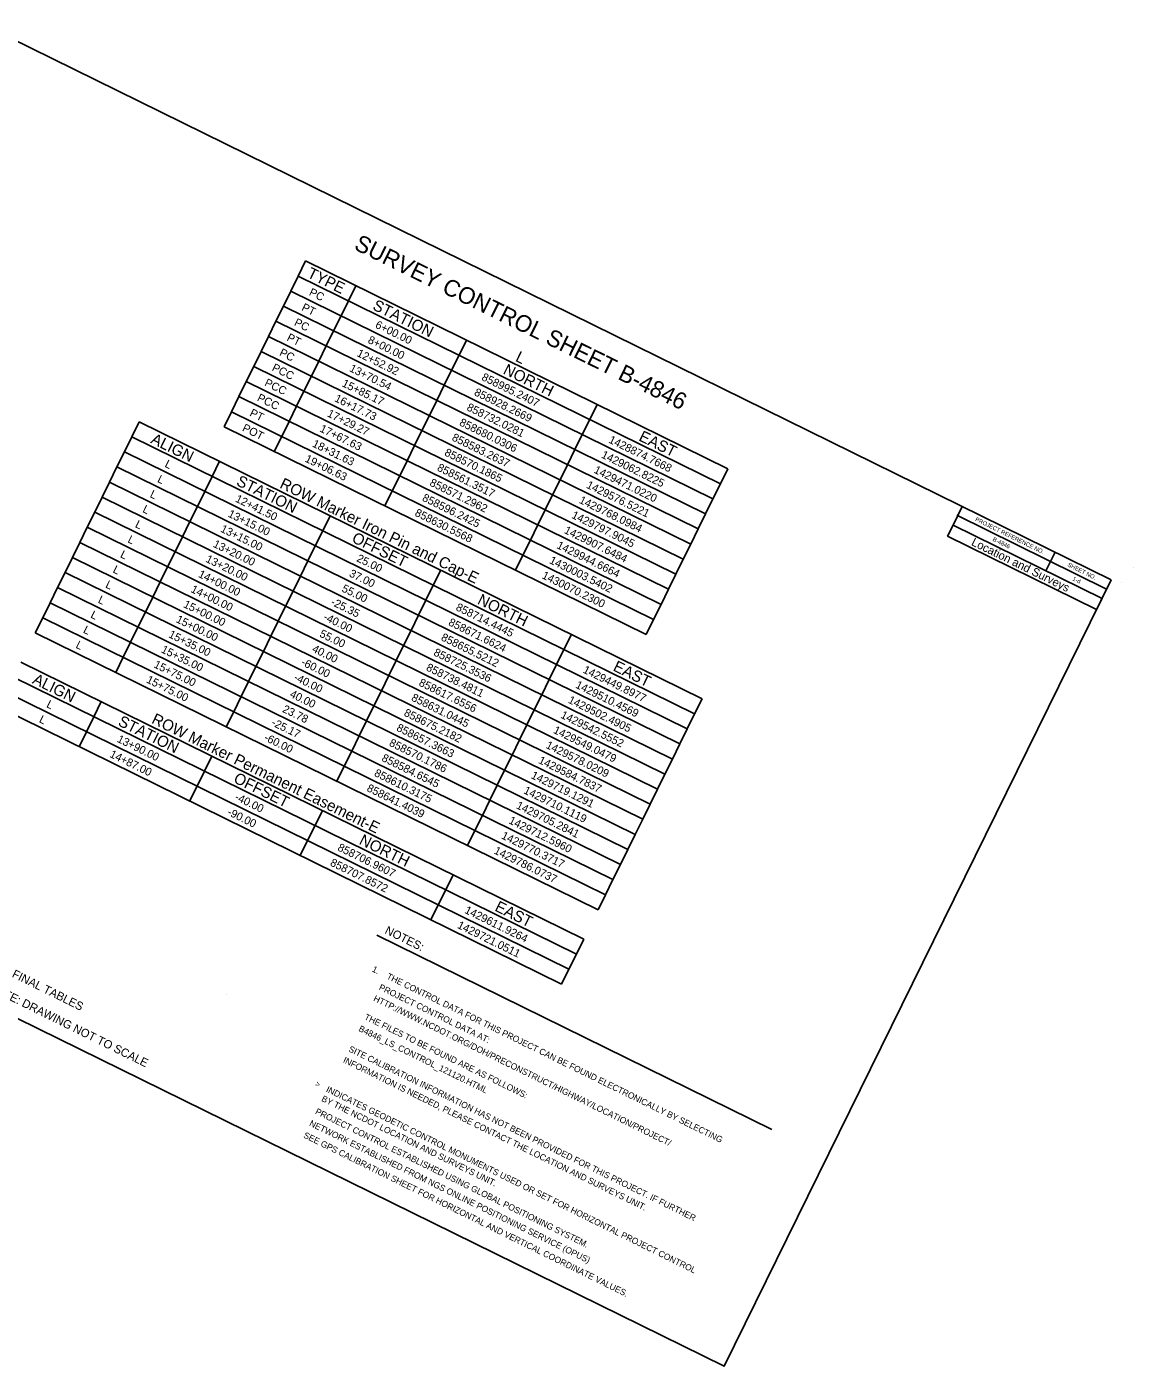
# Model space of a CAD drawing. Extents: x 1428428 to 1430511, y 857911 to 859585.
# Drawn here: x 1429129 to 1430511, y 857911 to 859585 of the extents above; entities that cross this region are included whole.
import ezdxf

# ---------------------------------------------------------------- set-up
doc = ezdxf.new("R2010")
doc.units = 0
for name, color, linetype in [('CTL Sheet Border CELL', 7, 'Continuous'), ('CTL Sheet Notes CELL', 7, 'Continuous'), ('CTL Sheet Table Cell', 7, 'Continuous'), ('CTL Sheet Text', 7, 'Continuous'), ('Sheet Title CELL', 7, 'Continuous')]:
    doc.layers.add(name, color=color, linetype=linetype)

msp = doc.modelspace()

# ---------------------------------------------------------------- linework, layer by layer
at = {"layer": 'CTL Sheet Border CELL'}
for p, q in [((1430297.8, 858985.3), (1430286.3, 858961.8)), ((1430291, 858974.1), (1430478.3, 858881.9)), ((1430413.8, 858928.2), (1430402.3, 858904.8)), ((1430511.5, 858909.2), (1430511.5, 858909.2)), ((1430496.9, 858890.3), (1430496.9, 858890.3)), ((1430496.9, 858890.3), (1430496.9, 858890.3))]:
    msp.add_line(p, q, dxfattribs=at)
for points in [[(1430484, 858893.6), (1429079.6, 859584.7), (1428595.9, 858601.6), (1430000.3, 857910.6)], [(1430286.3, 858961.8), (1430472.5, 858870.2), (1430465.7, 858856.4), (1430279.5, 858948.1)]]:
    msp.add_lwpolyline(points, close=True, dxfattribs=at)
at = {"layer": 'CTL Sheet Notes CELL'}
msp.add_line((1429566.2, 858449.5), (1430060, 858206.5), dxfattribs=at)
at = {"layer": 'CTL Sheet Table Cell'}
for p, q in [((1429477.1, 859292), (1429467.9, 859273.2)), ((1429477.1, 859292), (1430004.7, 859032.4)), ((1429467.9, 859273.2), (1429458.6, 859254.3)), ((1429467.9, 859273.2), (1429995.5, 859013.6)), ((1429458.6, 859254.3), (1429449.3, 859235.5)), ((1429458.6, 859254.3), (1429986.2, 858994.7)), ((1429540, 859261.1), (1429530.7, 859242.3)), ((1429449.3, 859235.5), (1429440.1, 859216.7)), ((1429449.3, 859235.5), (1429976.9, 858975.9)), ((1429530.7, 859242.3), (1429521.4, 859223.4)), ((1429440.1, 859216.7), (1429430.8, 859197.8)), ((1429440.1, 859216.7), (1429967.7, 858957.1)), ((1429521.4, 859223.4), (1429512.1, 859204.6)), ((1429430.8, 859197.8), (1429421.5, 859179)), ((1429430.8, 859197.8), (1429958.4, 858938.2)), ((1429512.1, 859204.6), (1429502.9, 859185.8)), ((1429502.9, 859185.8), (1429493.6, 859166.9)), ((1429678.1, 859193.1), (1429668.9, 859174.3)), ((1429421.5, 859179), (1429412.2, 859160.1)), ((1429421.5, 859179), (1429949.1, 858919.4)), ((1429493.6, 859166.9), (1429484.3, 859148.1)), ((1429668.9, 859174.3), (1429659.6, 859155.4)), ((1429412.2, 859160.1), (1429403, 859141.3)), ((1429412.2, 859160.1), (1429939.8, 858900.5)), ((1429484.3, 859148.1), (1429475.1, 859129.2)), ((1429659.6, 859155.4), (1429650.3, 859136.6)), ((1429403, 859141.3), (1429393.7, 859122.4)), ((1429403, 859141.3), (1429930.6, 858881.7)), ((1429650.3, 859136.6), (1429641, 859117.8)), ((1429393.7, 859122.4), (1429384.4, 859103.6)), ((1429393.7, 859122.4), (1429921.3, 858862.8)), ((1429475.1, 859129.2), (1429465.8, 859110.4)), ((1429641, 859117.8), (1429631.8, 859098.9)), ((1429841.4, 859112.8), (1429832.2, 859093.9)), ((1429384.4, 859103.6), (1429375.2, 859084.8)), ((1429384.4, 859103.6), (1429912, 858844)), ((1429465.8, 859110.4), (1429456.5, 859091.5)), ((1429631.8, 859098.9), (1429622.5, 859080.1)), ((1429269.1, 859091), (1429259.8, 859072.2)), ((1429269.1, 859091), (1429972.6, 858744.9)), ((1429375.2, 859084.8), (1429902.7, 858825.2)), ((1429456.5, 859091.5), (1429447.2, 859072.7)), ((1429622.5, 859080.1), (1429613.2, 859061.2)), ((1429832.2, 859093.9), (1429822.9, 859075.1)), ((1429259.8, 859072.2), (1429250.6, 859053.4)), ((1429259.8, 859072.2), (1429963.3, 858726.1)), ((1429447.2, 859072.7), (1429438, 859053.9)), ((1429822.9, 859075.1), (1429813.6, 859056.2)), ((1429250.6, 859053.4), (1429241.3, 859034.5)), ((1429250.6, 859053.4), (1429954, 858707.2)), ((1429613.2, 859061.2), (1429604, 859042.4)), ((1429813.6, 859056.2), (1429804.3, 859037.4)), ((1429241.3, 859034.5), (1429232, 859015.7)), ((1429241.3, 859034.5), (1429944.7, 858688.4)), ((1429369.6, 859041.6), (1429360.3, 859022.7)), ((1429604, 859042.4), (1429594.7, 859023.5)), ((1429804.3, 859037.4), (1429795.1, 859018.6)), ((1430004.7, 859032.4), (1429995.5, 859013.6)), ((1429232, 859015.7), (1429222.7, 858996.8)), ((1429232, 859015.7), (1429935.5, 858669.5)), ((1429360.3, 859022.7), (1429351.1, 859003.9)), ((1429594.7, 859023.5), (1429585.4, 859004.7)), ((1429795.1, 859018.6), (1429785.8, 858999.7)), ((1429995.5, 859013.6), (1429986.2, 858994.7)), ((1429222.7, 858996.8), (1429213.5, 858978)), ((1429222.7, 858996.8), (1429926.2, 858650.7)), ((1429351.1, 859003.9), (1429341.8, 858985.1)), ((1429585.4, 859004.7), (1429576.1, 858985.9)), ((1429785.8, 858999.7), (1429776.5, 858980.9)), ((1429341.8, 858985.1), (1429332.5, 858966.2)), ((1429776.5, 858980.9), (1429767.3, 858962)), ((1429986.2, 858994.7), (1429976.9, 858975.9)), ((1429213.5, 858978), (1429204.2, 858959.1)), ((1429213.5, 858978), (1429916.9, 858631.8)), ((1429332.5, 858966.2), (1429323.2, 858947.4)), ((1429507.8, 858973.6), (1429498.5, 858954.8)), ((1429767.3, 858962), (1429758, 858943.2)), ((1429976.9, 858975.9), (1429967.7, 858957.1)), ((1429204.2, 858959.1), (1429194.9, 858940.3)), ((1429204.2, 858959.1), (1429907.7, 858613)), ((1429323.2, 858947.4), (1429314, 858928.5)), ((1429498.5, 858954.8), (1429489.2, 858935.9)), ((1429967.7, 858957.1), (1429958.4, 858938.2)), ((1429194.9, 858940.3), (1429185.7, 858921.5)), ((1429194.9, 858940.3), (1429898.4, 858594.2)), ((1429314, 858928.5), (1429304.7, 858909.7)), ((1429489.2, 858935.9), (1429480, 858917.1)), ((1429758, 858943.2), (1429748.7, 858924.4)), ((1429958.4, 858938.2), (1429949.1, 858919.4)), ((1429185.7, 858921.5), (1429176.4, 858902.6)), ((1429185.7, 858921.5), (1429889.1, 858575.3)), ((1429480, 858917.1), (1429470.7, 858898.2)), ((1429748.7, 858924.4), (1429739.4, 858905.5)), ((1429949.1, 858919.4), (1429939.8, 858900.5)), ((1429176.4, 858902.6), (1429167.1, 858883.8)), ((1429176.4, 858902.6), (1429879.8, 858556.5)), ((1429304.7, 858909.7), (1429295.4, 858890.9)), ((1429470.7, 858898.2), (1429461.4, 858879.4)), ((1429646, 858905.6), (1429636.7, 858886.8)), ((1429939.8, 858900.5), (1429930.6, 858881.7)), ((1429167.1, 858883.8), (1429157.8, 858864.9)), ((1429167.1, 858883.8), (1429870.6, 858537.6)), ((1429295.4, 858890.9), (1429286.1, 858872)), ((1429461.4, 858879.4), (1429452.1, 858860.5)), ((1429636.7, 858886.8), (1429627.4, 858867.9)), ((1429930.6, 858881.7), (1429921.3, 858862.8)), ((1429157.8, 858864.9), (1429148.6, 858846.1)), ((1429157.8, 858864.9), (1429861.3, 858518.8)), ((1429286.1, 858872), (1429276.9, 858853.2)), ((1429627.4, 858867.9), (1429618.1, 858849.1)), ((1429921.3, 858862.8), (1429912, 858844)), ((1429148.6, 858846.1), (1429139.3, 858827.2)), ((1429148.6, 858846.1), (1429852, 858499.9)), ((1429276.9, 858853.2), (1429267.6, 858834.3)), ((1429452.1, 858860.5), (1429442.9, 858841.7)), ((1429618.1, 858849.1), (1429608.9, 858830.2)), ((1429267.6, 858834.3), (1429258.3, 858815.5)), ((1429442.9, 858841.7), (1429433.6, 858822.9)), ((1429608.9, 858830.2), (1429599.6, 858811.4)), ((1429912, 858844), (1429902.7, 858825.2)), ((1429139.3, 858827.2), (1429842.8, 858481.1)), ((1429258.3, 858815.5), (1429249.1, 858796.6)), ((1429433.6, 858822.9), (1429424.3, 858804)), ((1429599.6, 858811.4), (1429590.3, 858792.6)), ((1429809.3, 858825.3), (1429800, 858806.4)), ((1429249.1, 858796.6), (1429239.8, 858777.8)), ((1429424.3, 858804), (1429415.1, 858785.2)), ((1429800, 858806.4), (1429790.7, 858787.6)), ((1429121.3, 858790.7), (1429824.7, 858444.5)), ((1429415.1, 858785.2), (1429405.8, 858766.3)), ((1429590.3, 858792.6), (1429581, 858773.7)), ((1429790.7, 858787.6), (1429781.4, 858768.7)), ((1429112, 858771.8), (1429815.5, 858425.7)), ((1429405.8, 858766.3), (1429396.5, 858747.5)), ((1429581, 858773.7), (1429571.8, 858754.9)), ((1429781.4, 858768.7), (1429772.2, 858749.9)), ((1429102.7, 858753), (1429806.2, 858406.9)), ((1429396.5, 858747.5), (1429387.2, 858728.6)), ((1429571.8, 858754.9), (1429562.5, 858736)), ((1429772.2, 858749.9), (1429762.9, 858731)), ((1429972.6, 858744.9), (1429963.3, 858726.1)), ((1429093.5, 858734.2), (1429796.9, 858388)), ((1429221.8, 858741.2), (1429212.5, 858722.4)), ((1429387.2, 858728.6), (1429378, 858709.8)), ((1429562.5, 858736), (1429553.2, 858717.2)), ((1429762.9, 858731), (1429753.6, 858712.2)), ((1429212.5, 858722.4), (1429203.2, 858703.5)), ((1429553.2, 858717.2), (1429544, 858698.3)), ((1429753.6, 858712.2), (1429744.4, 858693.4)), ((1429963.3, 858726.1), (1429954, 858707.2)), ((1429203.2, 858703.5), (1429194, 858684.7)), ((1429544, 858698.3), (1429534.7, 858679.5)), ((1429954, 858707.2), (1429944.7, 858688.4)), ((1429534.7, 858679.5), (1429525.4, 858660.7)), ((1429744.4, 858693.4), (1429735.1, 858674.5)), ((1429944.7, 858688.4), (1429935.5, 858669.5)), ((1429360, 858673.2), (1429350.7, 858654.4)), ((1429525.4, 858660.7), (1429516.1, 858641.8)), ((1429735.1, 858674.5), (1429725.8, 858655.7)), ((1429935.5, 858669.5), (1429926.2, 858650.7)), ((1429350.7, 858654.4), (1429341.4, 858635.6)), ((1429725.8, 858655.7), (1429716.5, 858636.8)), ((1429926.2, 858650.7), (1429916.9, 858631.8)), ((1429341.4, 858635.6), (1429332.1, 858616.7)), ((1429716.5, 858636.8), (1429707.3, 858618)), ((1429916.9, 858631.8), (1429907.7, 858613)), ((1429707.3, 858618), (1429698, 858599.1)), ((1429907.7, 858613), (1429898.4, 858594.2)), ((1429498.1, 858605.3), (1429488.9, 858586.4)), ((1429698, 858599.1), (1429688.7, 858580.3)), ((1429898.4, 858594.2), (1429889.1, 858575.3)), ((1429488.9, 858586.4), (1429479.6, 858567.6)), ((1429688.7, 858580.3), (1429679.4, 858561.5)), ((1429479.6, 858567.6), (1429470.3, 858548.7)), ((1429889.1, 858575.3), (1429879.8, 858556.5)), ((1429879.8, 858556.5), (1429870.6, 858537.6)), ((1429870.6, 858537.6), (1429861.3, 858518.8)), ((1429661.4, 858524.9), (1429652.2, 858506.1)), ((1429861.3, 858518.8), (1429852, 858499.9)), ((1429652.2, 858506.1), (1429642.9, 858487.2)), ((1429852, 858499.9), (1429842.8, 858481.1)), ((1429642.9, 858487.2), (1429633.6, 858468.4)), ((1429824.7, 858444.5), (1429815.5, 858425.7)), ((1429815.5, 858425.7), (1429806.2, 858406.9)), ((1429806.2, 858406.9), (1429796.9, 858388))]:
    msp.add_line(p, q, dxfattribs=at)
at = {"layer": 'Sheet Title CELL'}
msp.add_line((1429378.1, 858374.6), (1429378.1, 858374.6), dxfattribs=at)

# ---------------------------------------------------------------- texts
at = {"layer": 'CTL Sheet Border CELL'}
for s, height, rotation, p in [('SURVEY CONTROL SHEET B-4846', 20.87, 333.8001, (1429536.3, 859307.2)), ('PROJECT REFERENCE NO.', 5.217, 333.8001, (1430313.5, 858967.4)), ('Location and Surveys', 10.435, 333.8001, (1430308.3, 858937.2)), ('B-4846', 5.22, 333.8001, (1430335.2, 858942.4)), ('SHEET NO.', 5.22, 333.8001, (1430428.8, 858910.6)), ('1-d', 5.22, 333.8001, (1430435, 858893.2)), ('     FINAL TABLES', 10.435, 333.6949, (1429091.9, 858406.1)), ('NOTE: DRAWING NOT TO SCALE', 10.435, 333.6949, (1429079.8, 858381.5))]:
    msp.add_text(s, height=height, rotation=rotation, dxfattribs=at).set_placement(p)
at = {"layer": 'CTL Sheet Notes CELL'}
for s, height, rotation, p in [('TYPE', 14, 333.8001, (1429478, 859272.1)), ('STATION', 14, 333.8001, (1429559.8, 859231.9)), ('NORTH', 14, 333.8001, (1429723, 859151.6)), ('L', 14, 333.8001, (1429738.3, 859167.4)), ('EAST', 14, 333.8001, (1429892.5, 859068.1)), ('ALIGN', 14, 333.8001, (1429282.5, 859064.9)), ('STATION', 14, 333.8001, (1429389.4, 859012.3)), ('ROW Marker Iron Pin and Cap-E', 14, 333.8001, (1429443.7, 859009)), ('OFFSET', 14, 333.8001, (1429533.8, 858941.3)), ('NORTH', 14, 333.8001, (1429690.8, 858864)), ('EAST', 14, 333.8001, (1429860.3, 858780.6)), ('ALIGN', 14, 333.8001, (1429134.7, 858764.6)), ('STATION', 14, 333.8001, (1429241.6, 858712)), ('ROW Marker Permanent Easement-E', 14, 333.8001, (1429283.5, 858714.8)), ('OFFSET', 14, 333.8001, (1429386, 858640.9)), ('NORTH', 14, 333.8001, (1429543, 858563.7)), ('EAST', 14, 333.8001, (1429712.5, 858480.3)), ('NOTES:', 10.43, 333.6949, (1429575.3, 858452)), ('1.    THE CONTROL DATA FOR THIS PROJECT CAN BE FOUND ELECTRONICALLY BY SELECTING', 7.826, 333.8001, (1429559.4, 858404.3)), ('PROJECT CONTROL DATA AT:', 7.826, 333.8001, (1429568, 858381.6)), ('HTTP://WWW.NCDOT.ORG/DOH/PRECONSTRUCT/HIGHWAY/LOCATION/PROJECT/', 7.826, 333.8001, (1429561.2, 858367.7)), ('THE FILES TO BE FOUND ARE AS FOLLOWS:', 7.826, 333.8001, (1429549.8, 858344.5)), ('B4846_LS_CONTROL_121120.HTML', 7.826, 333.8001, (1429542.6, 858329.9)), ('SITE CALIBRATION INFORMATION HAS NOT BEEN PROVIDED FOR THIS PROJECT. IF FURTHER', 7.826, 333.8001, (1429530, 858304.4)), ('INFORMATION IS NEEDED, PLEASE CONTACT THE LOCATION AND SURVEYS UNIT.', 7.826, 333.8001, (1429523.2, 858290.6)), ('>', 7.34, 333.6948, (1429488.2, 858261.1)), ('INDICATES GEODETIC CONTROL MONUMENTS USED OR SET FOR HORIZONTAL PROJECT CONTROL', 7.826, 333.6949, (1429502, 858254.1)), ('BY THE NCDOT LOCATION AND SURVEYS UNIT.', 7.826, 333.6949, (1429496.2, 858242.4)), ('PROJECT CONTROL ESTABLISHED USING GLOBAL POSITIONING SYSTEM.', 7.826, 333.6949, (1429488.4, 858226.4)), ('NETWORK ESTABLISHED FROM NGS ONLINE POSITIONING SERVICE (OPUS)', 7.826, 333.6949, (1429481.1, 858211.6)), ('SEE GPS CALIBRATION SHEET FOR HORIZONTAL AND VERTICAL COORDINATE VALUES.', 7.826, 333.6949, (1429473.7, 858196.7))]:
    msp.add_text(s, height=height, rotation=rotation, dxfattribs=at).set_placement(p)
at = {"layer": 'CTL Sheet Text'}
for s, p in [('PC ', (1429480.6, 859249.7)), ('PT ', (1429471.3, 859230.8)), ('PC ', (1429462, 859212)), ('6+00.00', (1429563.3, 859209)), ('PT ', (1429452.8, 859193.1)), ('8+00.00', (1429554, 859190.1)), ('PC ', (1429443.5, 859174.3)), ('12+52.92', (1429540.3, 859173.5)), ('PCC', (1429434.2, 859155.5)), ('13+70.54', (1429531, 859154.6)), ('858995.2407', (1429696.2, 859143.6)), ('PCC', (1429424.9, 859136.6)), ('15+85.17', (1429521.7, 859135.8)), ('858928.2669', (1429686.9, 859124.7)), ('PCC', (1429415.7, 859117.8)), ('16+17.73', (1429512.4, 859117)), ('858732.0281', (1429677.6, 859105.9)), ('PT ', (1429406.4, 859098.9)), ('17+29.27', (1429503.2, 859098.1)), ('POT', (1429397.1, 859080.1)), ('17+67.63', (1429493.9, 859079.3)), ('858680.0306', (1429668.4, 859087)), ('18+31.63', (1429484.6, 859060.4)), ('858583.2637', (1429659.1, 859068.2)), ('1428874.7668', (1429855, 859065.4)), ('19+06.63', (1429475.4, 859041.6)), ('858570.1865', (1429649.8, 859049.4)), ('1429062.8225', (1429845.8, 859046.6)), ('L', (1429300.3, 859035)), ('858561.3517', (1429640.6, 859030.5)), ('1429471.0220', (1429836.5, 859027.7)), ('L', (1429291, 859016.2)), ('858571.2962', (1429631.3, 859011.7)), ('1429576.5221', (1429827.2, 859008.9)), ('L', (1429281.7, 858997.3)), ('12+41.50', (1429388.4, 858991.6)), ('858596.2425', (1429622, 858992.8)), ('1429768.0984', (1429818, 858990)), ('L', (1429272.5, 858978.5)), ('13+15.00', (1429379.2, 858972.8)), ('858630.5568', (1429612.7, 858974)), ('L', (1429263.2, 858959.7)), ('1429797.9045', (1429808.7, 858971.2)), ('L', (1429253.9, 858940.8)), ('13+15.00', (1429369.9, 858954)), ('1429907.6484', (1429799.4, 858952.3)), ('L', (1429244.6, 858922)), ('13+20.00', (1429360.6, 858935.1)), ('1429944.6664', (1429790.1, 858933.5)), ('13+20.00', (1429351.4, 858916.3)), ('25.00', (1429540, 858917.1)), ('1430003.5402', (1429780.9, 858914.7)), ('L', (1429235.4, 858903.1)), ('14+00.00', (1429342.1, 858897.4)), ('37.00', (1429530.7, 858898.2)), ('1430070.2300', (1429771.6, 858895.8)), ('L', (1429226.1, 858884.3)), ('14+00.00', (1429332.8, 858878.6)), ('55.00', (1429521.4, 858879.4)), ('L', (1429216.8, 858865.4)), ('15+00.00', (1429323.5, 858859.7)), ('-25.35', (1429507.7, 858862.7)), ('858714.4445', (1429664, 858856)), ('L', (1429207.5, 858846.6)), ('15+00.00', (1429314.3, 858840.9)), ('-40.00', (1429498.4, 858843.9)), ('858671.6624', (1429654.7, 858837.2)), ('L', (1429198.3, 858827.8)), ('15+35.00', (1429305, 858822.1)), ('55.00', (1429493.6, 858822.9)), ('L', (1429189, 858808.9)), ('858655.5212', (1429645.5, 858818.4)), ('15+35.00', (1429295.7, 858803.2)), ('40.00', (1429484.3, 858804)), ('858725.3536', (1429636.2, 858799.5)), ('15+75.00', (1429286.5, 858784.4)), ('-60.00', (1429470.6, 858787.4)), ('858738.4811', (1429626.9, 858780.7)), ('1429449.8977', (1429822.9, 858777.9)), ('15+75.00', (1429277.2, 858765.5)), ('-40.00', (1429461.4, 858768.5)), ('858617.6556', (1429617.7, 858761.8)), ('1429510.4569', (1429813.6, 858759)), ('40.00', (1429456.5, 858747.5)), ('858631.0445', (1429608.4, 858743)), ('1429502.4905', (1429804.3, 858740.2)), ('L', (1429152.4, 858734.7)), ('23.78', (1429447.3, 858728.7)), ('858675.2182', (1429599.1, 858724.1)), ('1429542.5552', (1429795, 858721.4)), ('L', (1429143.2, 858715.8)), ('-25.17', (1429433.5, 858712)), ('858657.3663', (1429589.8, 858705.3)), ('13+90.00', (1429240.6, 858691.3)), ('-60.00', (1429424.3, 858693.2)), ('858570.1786', (1429580.6, 858686.5)), ('1429549.0479', (1429785.8, 858702.5)), ('14+87.00', (1429231.4, 858672.4)), ('1429578.0209', (1429776.5, 858683.7)), ('858584.6545', (1429571.3, 858667.6)), ('1429584.7837', (1429767.2, 858664.8)), ('858610.3175', (1429562, 858648.8)), ('1429719.1291', (1429758, 858646)), ('858641.4039', (1429552.7, 858629.9)), ('1429710.1119', (1429748.7, 858627.1)), ('-40.00', (1429387.7, 858618.9)), ('1429705.2841', (1429739.4, 858608.3)), ('-90.00', (1429378.4, 858600.1)), ('1429712.5960', (1429730.1, 858589.5)), ('1429770.3717', (1429720.9, 858570.6)), ('858706.9607', (1429516.2, 858555.7)), ('858707.8572', (1429506.9, 858536.8)), ('1429786.0737', (1429711.6, 858551.8)), ('1429611.9264', (1429675, 858477.5)), ('1429721.0511', (1429665.8, 858458.7))]:
    msp.add_text(s, height=10, rotation=333.8001, dxfattribs=at).set_placement(p)

doc.saveas('drawing.dxf')
